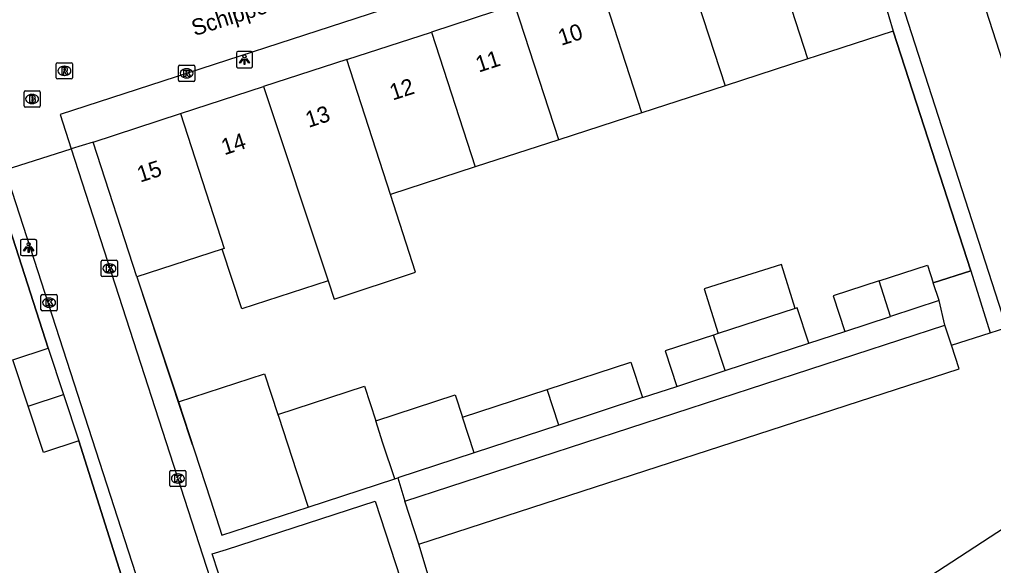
# Model space of a CAD drawing. Extents: x 159377 to 159983, y 382996 to 383595.
# Drawn here: x 159523.6 to 159583.7, y 383066.1 to 383099.8 of the extents above; entities that cross this region are included whole.
import ezdxf

# ---------------------------------------------------------------- set-up
doc = ezdxf.new("R2010")
doc.units = 0
for name, color, linetype in [('IMGEO_Brandkraan', 7, 'Continuous'), ('IMGEO_Kolk', 7, 'Continuous'), ('IMGEO_Lichtpunt', 7, 'Continuous'), ('IMGEO_Muur', 7, 'Continuous'), ('IMGEO_Openbare_ruimte_label', 7, 'Continuous'), ('IMGEO_Pand', 7, 'Continuous'), ('IMGEO_Pand_nummerreeks', 7, 'Continuous'), ('IMGEO_Rijbaan_lokaal_open', 7, 'Continuous'), ('IMGEO_Rioolput', 7, 'Continuous'), ('IMGEO_Voetpad_open', 7, 'Continuous')]:
    doc.layers.add(name, color=color, linetype=linetype)

msp = doc.modelspace()

# ---------------------------------------------------------------- linework, layer by layer
at = {"layer": 'IMGEO_Brandkraan'}
for p, q in [((159523.894, 383094.486), (159523.894, 383095.338)), ((159523.969, 383095.412), (159524.821, 383095.412)), ((159524.895, 383095.338), (159524.895, 383094.486)), ((159524.405, 383094.632), (159524.38, 383094.632)), ((159524.382, 383095.192), (159524.407, 383095.192)), ((159524.821, 383094.412), (159523.969, 383094.412))]:
    msp.add_line(p, q, dxfattribs=at)
for points in [[(159523.894, 383094.486), (159523.894, 383095.338)], [(159523.969, 383095.412), (159524.821, 383095.412)], [(159524.895, 383095.338), (159524.895, 383094.486)], [(159524.242, 383095.112), (159524.242, 383094.712), (159524.455, 383094.712)], [(159524.473, 383095.112), (159524.242, 383095.112)], [(159524.421, 383095.031), (159524.367, 383095.031), (159524.367, 383094.955)], [(159524.367, 383094.955), (159524.42, 383094.955)], [(159524.429, 383094.879), (159524.367, 383094.879), (159524.367, 383094.798)], [(159524.367, 383094.798), (159524.429, 383094.798)], [(159524.821, 383094.412), (159523.969, 383094.412)]]:
    msp.add_lwpolyline(points, dxfattribs=at)
for centre, radius, start, end in [((159523.971, 383095.336), 0.0765, 91.55205, 178.44795), ((159523.971, 383095.336), 0.0765, 91.55205, 178.44795), ((159524.819, 383095.336), 0.0765, 1.55205, 88.44795), ((159524.819, 383095.336), 0.0765, 1.55205, 88.44795), ((159524.422, 383094.993), 0.0379, 267.82845, 90.93552), ((159524.43, 383094.838), 0.0404, 269.87594, 90.50774), ((159524.461, 383094.963), 0.251, 268.66757, 293.53466), ((159524.477, 383094.967), 0.145, 59.4692, 91.53667), ((159524.502, 383095.014), 0.0922, 285.51372, 58.15012), ((159524.507, 383094.822), 0.105, 301.31148, 78.98903), ((159523.971, 383094.488), 0.0765, 181.55205, 268.44795), ((159523.971, 383094.488), 0.0765, 181.55205, 268.44795), ((159524.819, 383094.488), 0.0765, 271.55205, 358.44795), ((159524.819, 383094.488), 0.0765, 271.55205, 358.44795)]:
    msp.add_arc(centre, radius, start, end, dxfattribs=at)
for centre, major_axis, ratio, start_param, end_param in [((159524.381, 383094.912), (-0.387, 0.002), 0.722429, 4.712389, 7.853982), ((159524.406, 383094.912), (-0.39, 0.002), 0.717154, 1.570796, 4.712389)]:
    msp.add_ellipse(centre, major_axis=major_axis, ratio=ratio, start_param=start_param, end_param=end_param, dxfattribs=at)
at = {"layer": 'IMGEO_Kolk'}
for p, q in [((159533.428, 383096.072), (159533.428, 383096.924)), ((159533.503, 383096.998), (159534.355, 383096.998)), ((159533.916, 383096.778), (159533.941, 383096.778)), ((159534.429, 383096.924), (159534.429, 383096.072)), ((159534.355, 383095.998), (159533.503, 383095.998)), ((159533.939, 383096.218), (159533.914, 383096.218)), ((159528.662, 383084.041), (159528.662, 383084.893)), ((159528.737, 383084.967), (159529.589, 383084.967)), ((159529.15, 383084.747), (159529.175, 383084.747)), ((159529.663, 383084.893), (159529.663, 383084.041)), ((159529.589, 383083.967), (159528.737, 383083.967)), ((159529.173, 383084.187), (159529.148, 383084.187)), ((159524.941, 383081.93), (159524.941, 383082.782)), ((159525.016, 383082.856), (159525.868, 383082.856)), ((159525.429, 383082.636), (159525.454, 383082.636)), ((159525.942, 383082.782), (159525.942, 383081.93)), ((159525.452, 383082.076), (159525.427, 383082.076)), ((159525.868, 383081.856), (159525.016, 383081.856)), ((159532.888, 383071.089), (159532.888, 383071.941)), ((159532.963, 383072.015), (159533.815, 383072.015)), ((159533.376, 383071.795), (159533.401, 383071.795)), ((159533.889, 383071.941), (159533.889, 383071.089)), ((159533.399, 383071.235), (159533.374, 383071.235)), ((159533.815, 383071.015), (159532.963, 383071.015))]:
    msp.add_line(p, q, dxfattribs=at)
for points in [[(159533.428, 383096.072), (159533.428, 383096.924)], [(159533.503, 383096.998), (159534.355, 383096.998)], [(159533.749, 383096.698), (159533.872, 383096.698), (159533.872, 383096.547), (159534.002, 383096.698), (159534.166, 383096.698), (159534.02, 383096.547), (159534.173, 383096.298), (159534.021, 383096.298), (159533.936, 383096.462), (159533.872, 383096.395), (159533.872, 383096.298), (159533.749, 383096.298), (159533.749, 383096.698)], [(159534.429, 383096.924), (159534.429, 383096.072)], [(159534.355, 383095.998), (159533.503, 383095.998)], [(159528.662, 383084.041), (159528.662, 383084.893)], [(159528.737, 383084.967), (159529.589, 383084.967)], [(159528.983, 383084.667), (159529.106, 383084.667), (159529.106, 383084.516), (159529.236, 383084.667), (159529.4, 383084.667), (159529.254, 383084.516), (159529.407, 383084.267), (159529.255, 383084.267), (159529.17, 383084.431), (159529.106, 383084.364), (159529.106, 383084.267), (159528.983, 383084.267), (159528.983, 383084.667)], [(159529.663, 383084.893), (159529.663, 383084.041)], [(159529.589, 383083.967), (159528.737, 383083.967)], [(159524.941, 383081.93), (159524.941, 383082.782)], [(159525.016, 383082.856), (159525.868, 383082.856)], [(159525.942, 383082.782), (159525.942, 383081.93)], [(159525.262, 383082.556), (159525.385, 383082.556), (159525.385, 383082.405), (159525.515, 383082.556), (159525.679, 383082.556), (159525.533, 383082.405), (159525.686, 383082.156), (159525.534, 383082.156), (159525.449, 383082.32), (159525.385, 383082.253), (159525.385, 383082.156), (159525.262, 383082.156), (159525.262, 383082.556)], [(159525.868, 383081.856), (159525.016, 383081.856)], [(159532.888, 383071.089), (159532.888, 383071.941)], [(159532.963, 383072.015), (159533.815, 383072.015)], [(159533.889, 383071.941), (159533.889, 383071.089)], [(159533.209, 383071.715), (159533.332, 383071.715), (159533.332, 383071.564), (159533.462, 383071.715), (159533.626, 383071.715), (159533.48, 383071.564), (159533.633, 383071.315), (159533.481, 383071.315), (159533.396, 383071.479), (159533.332, 383071.412), (159533.332, 383071.315), (159533.209, 383071.315), (159533.209, 383071.715)], [(159533.815, 383071.015), (159532.963, 383071.015)]]:
    msp.add_lwpolyline(points, dxfattribs=at)
for centre, start, end in [((159533.505, 383096.922), 91.55205, 178.44795), ((159533.505, 383096.922), 91.55205, 178.44795), ((159534.353, 383096.922), 1.55205, 88.44795), ((159534.353, 383096.922), 1.55205, 88.44795), ((159533.505, 383096.074), 181.55205, 268.44795), ((159533.505, 383096.074), 181.55205, 268.44795), ((159534.353, 383096.074), 271.55205, 358.44795), ((159534.353, 383096.074), 271.55205, 358.44795), ((159528.739, 383084.891), 91.55205, 178.44795), ((159528.739, 383084.891), 91.55205, 178.44795), ((159529.587, 383084.891), 1.55205, 88.44795), ((159529.587, 383084.891), 1.55205, 88.44795), ((159528.739, 383084.043), 181.55205, 268.44795), ((159528.739, 383084.043), 181.55205, 268.44795), ((159529.587, 383084.043), 271.55205, 358.44795), ((159529.587, 383084.043), 271.55205, 358.44795), ((159525.018, 383082.78), 91.55205, 178.44795), ((159525.018, 383082.78), 91.55205, 178.44795), ((159525.866, 383082.78), 1.55205, 88.44795), ((159525.866, 383082.78), 1.55205, 88.44795), ((159525.018, 383081.932), 181.55205, 268.44795), ((159525.018, 383081.932), 181.55205, 268.44795), ((159525.866, 383081.932), 271.55205, 358.44795), ((159525.866, 383081.932), 271.55205, 358.44795), ((159532.965, 383071.939), 91.55205, 178.44795), ((159532.965, 383071.939), 91.55205, 178.44795), ((159533.813, 383071.939), 1.55205, 88.44795), ((159533.813, 383071.939), 1.55205, 88.44795), ((159532.965, 383071.091), 181.55205, 268.44795), ((159532.965, 383071.091), 181.55205, 268.44795), ((159533.813, 383071.091), 271.55205, 358.44795), ((159533.813, 383071.091), 271.55205, 358.44795)]:
    msp.add_arc(centre, 0.0765, start, end, dxfattribs=at)
for centre, major_axis, ratio, start_param, end_param in [((159533.915, 383096.498), (-0.387, 0.002), 0.722429, 4.712389, 7.853982), ((159533.94, 383096.498), (-0.39, 0.002), 0.717154, 1.570796, 4.712389), ((159529.149, 383084.467), (-0.387, 0.002), 0.722429, 4.712389, 7.853982), ((159529.174, 383084.467), (-0.39, 0.002), 0.717154, 1.570796, 4.712389), ((159525.428, 383082.356), (-0.387, 0.002), 0.722429, 4.712389, 7.853982), ((159525.453, 383082.356), (-0.39, 0.002), 0.717154, 1.570796, 4.712389), ((159533.375, 383071.515), (-0.387, 0.002), 0.722429, 4.712389, 7.853982), ((159533.4, 383071.515), (-0.39, 0.002), 0.717154, 1.570796, 4.712389)]:
    msp.add_ellipse(centre, major_axis=major_axis, ratio=ratio, start_param=start_param, end_param=end_param, dxfattribs=at)
at = {"layer": 'IMGEO_Lichtpunt'}
for p, q in [((159537.001, 383097.746), (159537.001, 383096.939)), ((159537.001, 383097.746), (159537.001, 383096.939)), ((159537.903, 383097.841), (159537.095, 383097.841)), ((159537.903, 383097.841), (159537.095, 383097.841)), ((159537.997, 383096.939), (159537.997, 383097.746)), ((159537.997, 383096.939), (159537.997, 383097.746)), ((159537.095, 383096.845), (159537.903, 383096.845)), ((159537.095, 383096.845), (159537.903, 383096.845)), ((159524.582, 383086.256), (159523.774, 383086.256)), ((159524.582, 383086.256), (159523.774, 383086.256)), ((159523.68, 383086.161), (159523.68, 383085.354)), ((159523.68, 383086.161), (159523.68, 383085.354)), ((159524.676, 383085.354), (159524.676, 383086.161)), ((159524.676, 383085.354), (159524.676, 383086.161)), ((159523.774, 383085.26), (159524.582, 383085.26)), ((159523.774, 383085.26), (159524.582, 383085.26))]:
    msp.add_line(p, q, dxfattribs=at)
for points in [[(159537.375, 383097.41), (159537.414, 383097.382), (159537.226, 383097.12), (159537.188, 383097.147), (159537.375, 383097.41)], [(159537.477, 383097.362), (159537.524, 383097.362), (159537.524, 383097.04), (159537.477, 383097.04), (159537.477, 383097.362)], [(159537.587, 383097.382), (159537.625, 383097.409), (159537.812, 383097.147), (159537.773, 383097.119), (159537.587, 383097.382)], [(159524.054, 383085.825), (159524.093, 383085.797), (159523.905, 383085.535), (159523.867, 383085.562), (159524.054, 383085.825)], [(159524.156, 383085.777), (159524.203, 383085.777), (159524.203, 383085.455), (159524.156, 383085.455), (159524.156, 383085.777)], [(159524.266, 383085.797), (159524.304, 383085.824), (159524.491, 383085.562), (159524.452, 383085.534), (159524.266, 383085.797)]]:
    msp.add_lwpolyline(points, dxfattribs=at)
for centre in [(159537.5, 383097.544), (159524.179, 383085.959)]:
    msp.add_circle(centre, 0.0994, dxfattribs=at)
for centre, start, end in [((159537.095, 383097.746), 90, 180), ((159537.095, 383097.746), 90, 180), ((159537.903, 383097.746), 0, 90), ((159537.903, 383097.746), 0, 90), ((159537.095, 383096.939), 180, 270), ((159537.095, 383096.939), 180, 270), ((159537.903, 383096.939), 270, 0), ((159537.903, 383096.939), 270, 360), ((159523.774, 383086.161), 90, 180), ((159523.774, 383086.161), 90, 180), ((159524.582, 383086.161), 0, 90), ((159524.582, 383086.161), 0, 90), ((159523.774, 383085.354), 180, 270), ((159523.774, 383085.354), 180, 270), ((159524.582, 383085.354), 270, 0), ((159524.582, 383085.354), 270, 360)]:
    msp.add_arc(centre, 0.0946, start, end, dxfattribs=at)
at = {"layer": 'IMGEO_Muur'}
for points in [[(159577.533, 383099.097), (159582.329, 383084.31)], [(159521.915, 383090.295), (159525.389, 383079.56)], [(159530.85, 383083.943), (159534.267, 383073.62)], [(159582.329, 383084.31), (159580.007, 383083.574)], [(159527.278, 383073.835), (159531.273, 383061.22)]]:
    msp.add_lwpolyline(points, dxfattribs=at)
at = {"layer": 'IMGEO_Pand'}
for points in [[(159572.256, 383097.384), (159569.577, 383105.707)], [(159564.446, 383104.041), (159567.152, 383095.728)], [(159562.01, 383094.058), (159559.316, 383102.376)], [(159576.724, 383101.831), (159577.533, 383099.097)], [(159554.184, 383100.71), (159549.045, 383099.042)], [(159556.888, 383092.396), (159554.184, 383100.71)], [(159543.819, 383097.345), (159549.045, 383099.042)], [(159549.045, 383099.042), (159551.737, 383090.724)], [(159577.533, 383099.097), (159572.778, 383097.554), (159572.256, 383097.384)], [(159543.819, 383097.345), (159538.679, 383095.677)], [(159546.51, 383089.027), (159543.819, 383097.345)], [(159572.256, 383097.384), (159567.152, 383095.728)], [(159533.546, 383094.01), (159538.679, 383095.677)], [(159538.679, 383095.677), (159542.654, 383083.696)], [(159567.152, 383095.728), (159562.01, 383094.058)], [(159562.01, 383094.058), (159556.888, 383092.396)], [(159528.151, 383092.259), (159533.546, 383094.01)], [(159533.546, 383094.01), (159536.246, 383085.695), (159536.129, 383085.657)], [(159530.85, 383083.943), (159528.151, 383092.259)], [(159556.888, 383092.396), (159551.737, 383090.724)], [(159551.737, 383090.724), (159546.51, 383089.027)], [(159542.654, 383083.696), (159543.03, 383082.562), (159548.062, 383084.231), (159546.51, 383089.027)], [(159536.129, 383085.657), (159530.85, 383083.943)], [(159542.654, 383083.696), (159537.327, 383081.967), (159536.129, 383085.657)], [(159571.485, 383082.006), (159570.629, 383084.713), (159565.861, 383083.206), (159566.732, 383080.451)], [(159576.661, 383083.7), (159579.647, 383084.677), (159580.007, 383083.574)], [(159576.661, 383083.7), (159573.828, 383082.773), (159574.54, 383080.585)], [(159577.366, 383081.509), (159576.661, 383083.7)], [(159580.361, 383082.489), (159580.007, 383083.574)], [(159571.485, 383082.006), (159566.732, 383080.451)], [(159572.318, 383079.858), (159571.606, 383082.046), (159571.485, 383082.006)], [(159580.361, 383082.489), (159577.366, 383081.509)], [(159590.076, 383081.989), (159594.612, 383075.126), (159554.73, 383049.152)], [(159574.54, 383080.585), (159577.366, 383081.509)], [(159547.401, 383070.111), (159580.718, 383080.97)], [(159581.119, 383079.733), (159580.718, 383080.97)], [(159566.447, 383080.358), (159563.462, 383079.381), (159564.173, 383077.194)], [(159566.732, 383080.451), (159566.447, 383080.358)], [(159567.156, 383078.17), (159566.447, 383080.358)], [(159548.258, 383067.467), (159581.591, 383078.278), (159581.119, 383079.733)], [(159567.156, 383078.17), (159572.318, 383079.858)], [(159524.149, 383075.977), (159523.205, 383078.84), (159525.389, 383079.56)], [(159525.389, 383079.56), (159526.334, 383076.698)], [(159556.179, 383076.998), (159561.346, 383078.689), (159562.057, 383076.502)], [(159533.432, 383076.248), (159538.735, 383077.972), (159539.558, 383075.456)], [(159564.173, 383077.194), (159567.156, 383078.17)], [(159539.558, 383075.456), (159544.911, 383077.206), (159545.601, 383075.064)], [(159524.149, 383075.977), (159526.334, 383076.698)], [(159526.334, 383076.698), (159527.278, 383073.835)], [(159545.601, 383075.064), (159550.509, 383076.67), (159550.955, 383075.289)], [(159550.955, 383075.289), (159556.179, 383076.998)], [(159556.887, 383074.811), (159556.179, 383076.998)], [(159533.432, 383076.248), (159535.399, 383070.199), (159536.109, 383068.015), (159541.423, 383069.753)], [(159562.057, 383076.502), (159556.887, 383074.811)], [(159527.278, 383073.835), (159525.093, 383073.114), (159524.149, 383075.977)], [(159539.558, 383075.456), (159539.588, 383075.354), (159540.709, 383071.936), (159541.423, 383069.753)], [(159546.776, 383071.503), (159546.046, 383073.683), (159545.601, 383075.064)], [(159551.662, 383073.102), (159550.955, 383075.289)], [(159556.887, 383074.811), (159551.662, 383073.102)], [(159551.662, 383073.102), (159546.958, 383071.563)], [(159541.423, 383069.753), (159546.776, 383071.503)], [(159546.776, 383071.503), (159546.958, 383071.563)], [(159548.258, 383067.467), (159547.401, 383070.111)]]:
    msp.add_lwpolyline(points, dxfattribs=at)
at = {"layer": 'IMGEO_Rijbaan_lokaal_open'}
for points in [[(159582.21, 383103.611), (159588.82, 383083.137)], [(159550.697, 383101.96), (159526.127, 383093.955), (159526.812, 383091.837)], [(159522.735, 383090.553), (159526.812, 383091.837)], [(159526.812, 383091.837), (159536.492, 383061.91), (159537.072, 383062.097)], [(159533.947, 383055.907), (159522.735, 383090.553)]]:
    msp.add_lwpolyline(points, dxfattribs=at)
at = {"layer": 'IMGEO_Rioolput'}
for p, q in [((159525.885, 383096.222), (159525.885, 383097.074)), ((159525.96, 383097.148), (159526.812, 383097.148)), ((159526.886, 383097.074), (159526.886, 383096.222)), ((159526.373, 383096.928), (159526.398, 383096.928)), ((159526.812, 383096.148), (159525.96, 383096.148)), ((159526.396, 383096.368), (159526.371, 383096.368))]:
    msp.add_line(p, q, dxfattribs=at)
for points in [[(159525.885, 383096.222), (159525.885, 383097.074)], [(159525.96, 383097.148), (159526.812, 383097.148)], [(159526.886, 383097.074), (159526.886, 383096.222)], [(159526.474, 383096.846), (159526.222, 383096.848), (159526.222, 383096.448)], [(159526.222, 383096.448), (159526.346, 383096.448), (159526.346, 383096.61), (159526.357, 383096.61)], [(159526.4, 383096.767), (159526.346, 383096.767), (159526.346, 383096.686)], [(159526.346, 383096.686), (159526.398, 383096.686)], [(159526.404, 383096.581), (159526.475, 383096.448), (159526.615, 383096.448), (159526.55, 383096.574)], [(159526.812, 383096.148), (159525.96, 383096.148)]]:
    msp.add_lwpolyline(points, dxfattribs=at)
for centre, radius, start, end in [((159525.962, 383097.072), 0.0765, 91.55205, 178.44795), ((159525.962, 383097.072), 0.0765, 91.55205, 178.44795), ((159526.81, 383097.072), 0.0765, 1.55205, 88.44795), ((159526.81, 383097.072), 0.0765, 1.55205, 88.44795), ((159526.356, 383096.557), 0.0533, 26.02933, 88.69889), ((159526.382, 383096.875), 0.19, 274.7715, 282.96867), ((159526.406, 383096.671), 0.0964, 77.00612, 93.18647), ((159526.42, 383096.728), 0.0378, 276.66336, 79.67722), ((159526.473, 383096.736), 0.109, 350.36119, 89.41601), ((159526.471, 383096.736), 0.112, 277.58423, 350.98172), ((159526.455, 383096.521), 0.108, 29.51342, 73.79051), ((159525.962, 383096.224), 0.0765, 181.55205, 268.44795), ((159525.962, 383096.224), 0.0765, 181.55205, 268.44795), ((159526.81, 383096.224), 0.0765, 271.55205, 358.44795), ((159526.81, 383096.224), 0.0765, 271.55205, 358.44795)]:
    msp.add_arc(centre, radius, start, end, dxfattribs=at)
for centre, major_axis, ratio, start_param, end_param in [((159526.372, 383096.648), (-0.387, 0.002), 0.722429, 4.712389, 7.853982), ((159526.397, 383096.648), (-0.39, 0.002), 0.717154, 1.570796, 4.712389)]:
    msp.add_ellipse(centre, major_axis=major_axis, ratio=ratio, start_param=start_param, end_param=end_param, dxfattribs=at)
at = {"layer": 'IMGEO_Voetpad_open'}
for points in [[(159588.82, 383083.137), (159584.26, 383081.67), (159577.654, 383102.133)], [(159582.329, 383084.31), (159577.533, 383099.097)], [(159528.151, 383092.259), (159526.812, 383091.837)], [(159525.389, 383079.56), (159521.915, 383090.295)], [(159530.85, 383083.943), (159533.432, 383076.248)], [(159580.007, 383083.574), (159582.329, 383084.31)], [(159582.329, 383084.31), (159583.508, 383080.491)], [(159580.718, 383080.97), (159580.361, 383082.489)], [(159583.508, 383080.491), (159584.535, 383080.817), (159589.756, 383082.472), (159590.076, 383081.989)], [(159572.318, 383079.858), (159574.54, 383080.585)], [(159581.119, 383079.733), (159583.508, 383080.491)], [(159562.057, 383076.502), (159564.173, 383077.194)], [(159531.273, 383061.22), (159527.278, 383073.835)], [(159546.958, 383071.563), (159547.401, 383070.111)], [(159537.072, 383062.097), (159535.513, 383066.876), (159536.383, 383067.146), (159545.563, 383070.117), (159547.119, 383065.338)], [(159554.73, 383049.152), (159552.839, 383052.245), (159548.258, 383067.467)]]:
    msp.add_lwpolyline(points, dxfattribs=at)

# ---------------------------------------------------------------- texts
at = {"layer": 'IMGEO_Openbare_ruimte_label'}
msp.add_text('Schippershof', height=1, rotation=17.76432, dxfattribs=at).set_placement((159534.42, 383098.782))
at = {"layer": 'IMGEO_Pand_nummerreeks'}
for s, rotation, p in [('10', 17.98502, (159557.047, 383098.191)), ('11', 17.98502, (159551.957, 383096.538)), ('12', 17.98502, (159546.649, 383094.815)), ('13', 17.98515, (159541.455, 383093.129)), ('14', 17.98502, (159536.259, 383091.442)), ('15', 17.98502, (159531.063, 383089.755))]:
    msp.add_text(s, height=1, rotation=rotation, dxfattribs=at).set_placement(p)

doc.saveas('drawing.dxf')
